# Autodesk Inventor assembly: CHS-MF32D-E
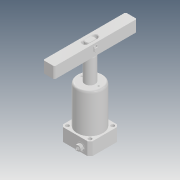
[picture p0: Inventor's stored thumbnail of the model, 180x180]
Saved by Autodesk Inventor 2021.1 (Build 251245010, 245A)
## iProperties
Created: 2020-02
Part Number: CHS-MF32D-E
Description: STEP AP214
Document SubType Name: Assembly
Designer: user
Title: chs-mf32d-e_asm.STEP
Revision Number: ÈÎºÎ
Sending System: SolidWorks 2016
Preprocessor: SwSTEP 2.0
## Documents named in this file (10)
- D:\Vault_2016\Projekty\Clamptek\Hydraulic\CHS\CHS-32\Inventor\CHS-MF32D-E\CHS-MF32D-E.iam
- D:\Vault_2016\Projekty\Clamptek\Hydraulic\CHS\CHS-32\Inventor\CHS-MF32D-E\CHS-32D-02-E_1_1.ipt
- D:\Vault_2016\Projekty\Clamptek\Hydraulic\CHS\CHS-32\Inventor\CHS-MF32D-E\CHS-32D-01_7.ipt
- D:\Vault_2016\Projekty\Clamptek\Hydraulic\CHS\CHS-32\Inventor\CHS-MF32D-E\CHS-TXF-01_2.ipt
- D:\Vault_2016\Projekty\Clamptek\Hydraulic\CHS\CHS-32\Inventor\CHS-MF32D-E\CHS-MF32-TXF-02_2.ipt
- D:\Vault_2016\Projekty\Clamptek\Hydraulic\CHS\CHS-32\Inventor\CHS-MF32D-E\CHS-MF32-TXF-03_2.ipt
- D:\Vault_2016\Projekty\Clamptek\Hydraulic\CHS\CHS-32\Inventor\CHS-MF32D-E\M6_2.ipt
- D:\Vault_2016\Projekty\Clamptek\Hydraulic\CHS\CHS-32\Inventor\CHS-MF32D-E\CHS-MF32-E-BT.ipt
- D:\Vault_2016\Projekty\Clamptek\Hydraulic\CHS\CHS-32\Inventor\CHS-MF32D-E\Öá8µ²È¦.ipt
- D:\Vault_2016\Projekty\Clamptek\Hydraulic\CHS\CHS-32\Inventor\CHS-MF32D-E\Xiaozhou.ipt
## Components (10 placed, 10 different names)
1. CHS-32D-02-E_1_1_1
2. CHS-32D-01_7_2
3. CHS-TXF-01_2_3
4. CHS-MF32-TXF-02_2_4
5. CHS-MF32-TXF-03_2_5
6. M6_2_6
7. CHS-MF32-E-BT_7
8. Öá8µ²È¦_8
9. Xiaozhou_9
10. Öá8µ²È¦_10
